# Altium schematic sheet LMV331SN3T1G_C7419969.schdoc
size 127 x 101 mm
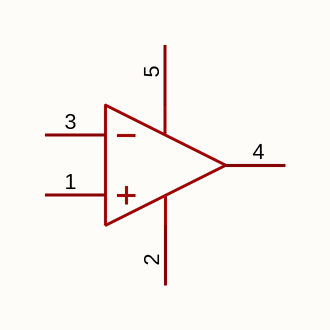
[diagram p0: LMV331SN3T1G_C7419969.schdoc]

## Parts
U?  lmv331sn3t1g_c7419969  [SOT-23-5_L3.0-W1.6-P0.95-LS2.8-BR]  (value not drawn)

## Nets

Not connected (* = marked no-connect by the designer): U? 1(IN+) 2(GND) 3(IN-) 4(OUT) 5(VDD)

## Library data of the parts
U? = lmv331sn3t1g_c7419969: 比较器数:单路;输入失调电压(Vos):500uV;输入偏置电流(Ib):6pA;轨到轨:轨到轨输入,轨到轨输出;; Manufacturer: TECH PUBLIC(台舟); AddInBom: yes; ModelId: 72410e292833493f86746b22636ce101; ModelTransform: 110.236,116.1415,0,0,0,0,0.002,0.001,0; Number of Channels: 单路; Vos - Input Offset Voltage: 500uV; Ib - Input Bias Current: 6pA; Propagation Delay Time: 77.5ns；59.4ns; Input Hysteresis Voltage (Vhys): 6mV; Common Mode Rejection Ratio(CMRR): 70dB; Output Type: 开漏; Output Mode: CMOS；TTL; Quiescent Current: 40uA; Maximum Power Supply Range (Vdd-Vss): 7V; Single Supply: 1.8V~5.5V; Dual Supply: 0.9V~2.75V；-2.75V~-0.9V; Input Offset Voltage Drift(Vos TC): 2uV/℃; Input Offset Current(Ios): 4pA; Response Time (tr): 5ns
